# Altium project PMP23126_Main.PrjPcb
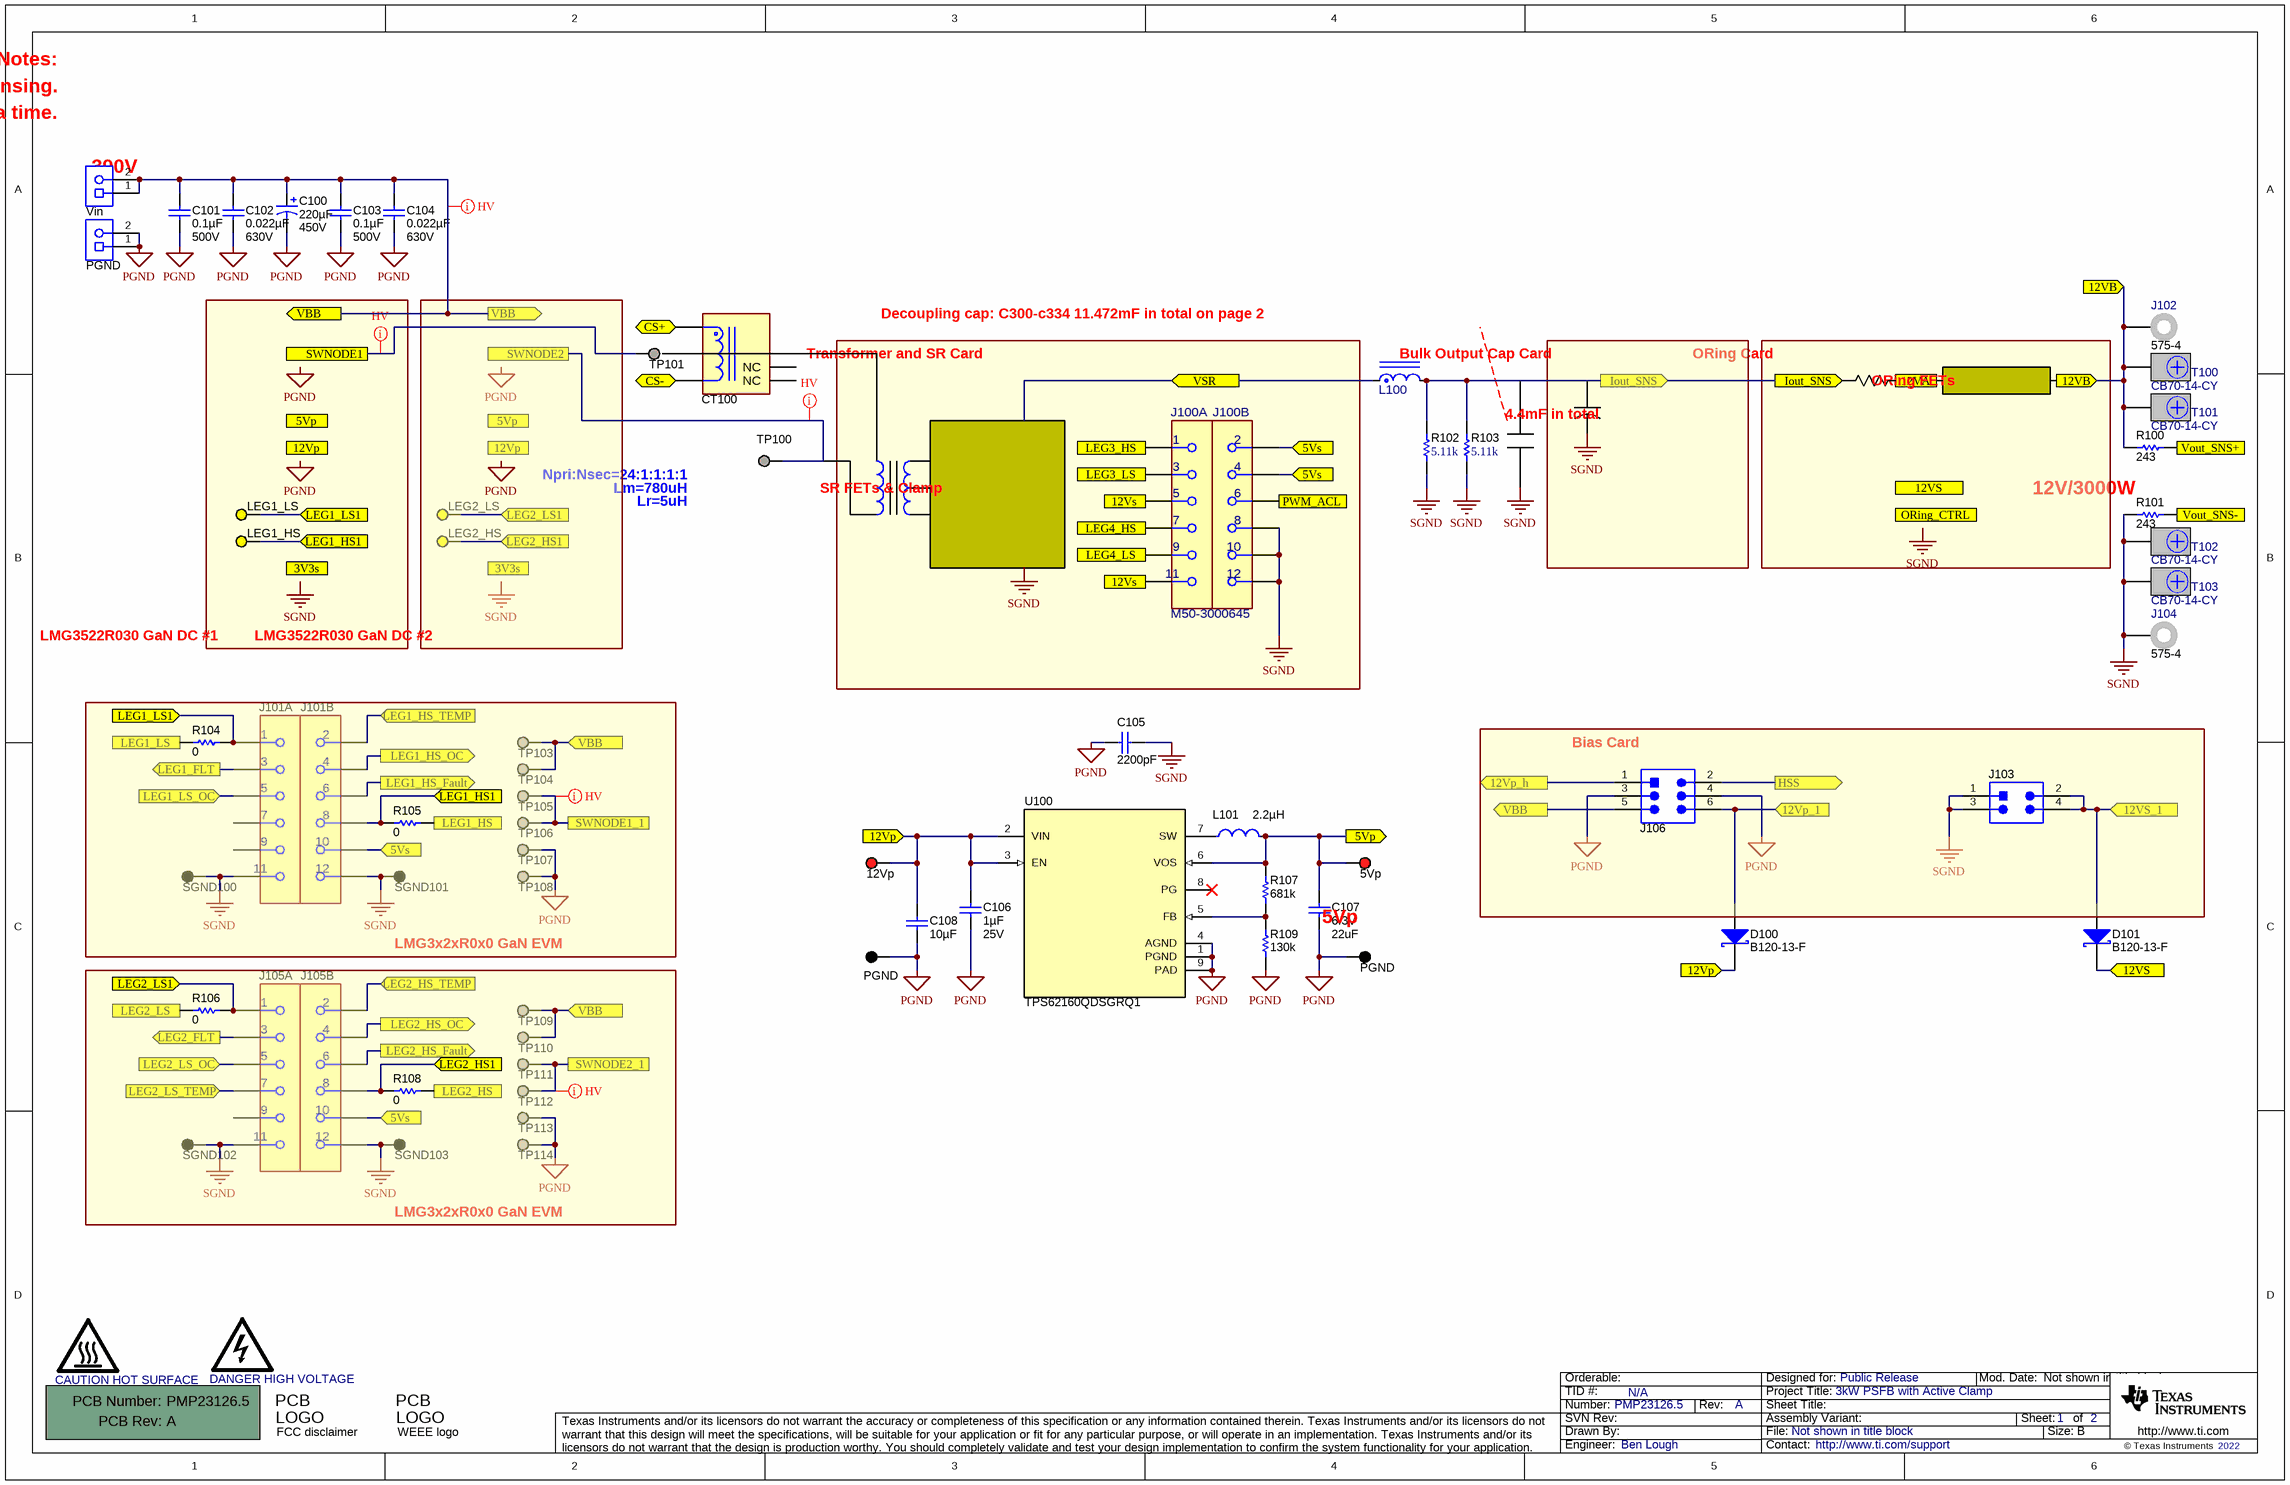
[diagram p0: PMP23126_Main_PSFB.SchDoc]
TID: N/A; TechSupport: http://www.ti.com/support; SCH_Rev: A; PRJ_Title: 3kW PSFB with Active Clamp; PRJ_Number: PMP23126.5; PRJ_Engineer: Ben Lough; PRJ_Customer: Public Release; PCB_Rev: A; PCB_Layout: Ben Lough; CopyrightYear: 2022
3 sheets, 168 parts. Net scope: flat (ports and power ports of the same name join across sheets).
Board file: PMP23126.5 Main Board.PcbDoc
Sheets:
  PMP23126_Main_PSFB.SchDoc
  PMP23126_Main_Controller.SchDoc
  Output_Decoupling.SchDoc

## Sheet PMP23126_Main_PSFB.SchDoc
size 431 x 279 mm; Date: Not shown in title block; ApprovedBy: Not shown in title block; CheckedBy: Not shown in title block; Author: Not shown in title block; CompanyName: Not shown in title block; Engineer: Not shown in title block; Organization: Not shown in title block; Address1: Not shown in title block; Address2: Not shown in title block; Address3: Not shown in title block; Address4: Not shown in title block; DocumentNumber: 1; Revision: Use project parameter SCH_Rev; SheetNumber: 1; SheetTotal: 2; PageSetup: Record=PageOptions¦CenterHorizontal=True¦CenterVertical=True¦PrintScale=1.00¦XCorrection=1.00¦YCorrection=1.00¦PrintKind=0¦BorderSize=5000000¦LeftOffset=0¦BottomOffset=0¦Orientation=2¦PaperLength=1000¦PaperWidth=1000¦Scale=100¦PaperSource=15¦PrintQuality=600¦MediaType=1¦DitherType=10¦PaperKind=Letter¦PrintScaleMode=1

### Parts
(Parts that share a designator on the sheet are numbered #1, #2 ... from top to bottom, then left to right.)
5Vp  5000  [Keystone5000]  (value not drawn)
12Vp  5000  [Keystone5000]  (value not drawn)
!PCB100  Printed Circuit Board  (value not drawn)  (mechanical)
C100  ValueDisplayed: 220µF  Value2: 450V  [TS-UP_3500x3000]  (hidden comment: LGU2W221MELC)
C101  ValueDisplayed: 0.1µF  Value2: 500V  [1812]  (hidden comment: VJ1812Y104KXEAT5Z)
C102  ValueDisplayed: 0.022µF  Value2: 630V  [1206]  (hidden comment: CL31B223KHHNNNE)
C103  ValueDisplayed: 0.1µF  Value2: 500V  [1812]  (hidden comment: VJ1812Y104KXEAT5Z)
C104  ValueDisplayed: 0.022µF  Value2: 630V  [1206]  (hidden comment: CL31B223KHHNNNE)
C105  ValueDisplayed: 2200pF  [E_900x700x900]  (hidden comment: DE6E3KJ222MN3A)
C106  Cap_F: 1µF  VDC_V: 25V  [0805_HV]  (hidden comment: C0805C105K3RACTU)
C107  VDC_V: 6.3V  ValueDisplayed: 22uF  [0805_HV]  (hidden comment: CL21A226KQQNNNE)
C108  ValueDisplayed: 10µF  [1206_180]  (hidden comment: GCM31CR71C106KA64L)
CT100  PAS6282NL  [FP-PAS6282NL_PTH_12MM5_4MM5-MFG]  (value not drawn)
D100  B120-13-F  [SMA]
D101  B120-13-F  [SMA]
J100#1  M50-3000645  [FP-M50-3000645_HDR12-MFG]  (part A of 2)
J100#2  M50-3000645  [FP-M50-3000645_HDR12-MFG]  (value not drawn)  (part B of 2)
J101  HLE-106-02-G-DV-BE-A  [FP-HLE-106-02-G-DV-BE-A_HDR12-MFG]  (value not drawn)  (parts A,B of 2)
J102  575-4  [Keystone_575-4]
J103  PBC02DAAN  [Sullins_PxC02DAAN]  (value not drawn)
J104  575-4  [Keystone_575-4]
J105  HLE-106-02-G-DV-BE-A  [FP-HLE-106-02-G-DV-BE-A_HDR12-MFG]  (value not drawn)  (parts A,B of 2)
J106  PBC03DAAN  [Sullins_PBC03DAAN]  (value not drawn)
L100  PAL6567.421NL  [FP-PAL6567.421NL_PTH_IND_34MM0_9MM5-MFG]  (value not drawn)
L101  Ind_H: 2.2µH  [FP-74438336010_SMD2-MFG]  (hidden comment: 74438336022)
LEG1_HS  5004  [Keystone5004]  (value not drawn)
LEG1_LS  5004  [Keystone5004]  (value not drawn)
LEG2_HS  5004  [Keystone5004]  (value not drawn)
LEG2_LS  5004  [Keystone5004]  (value not drawn)
LOGO100  CAUTION HOT SURFACE  [IEC_HotSurface_Small]  (no BOM)
LOGO101  DANGER HIGH VOLTAGE  [IEC_HighVoltage_Small]  (no BOM)
Logo102  FCC disclaimer  [FCC_disclaimer]  (no BOM)
Logo103  WEEE logo  [WEEE_Minimum]  (no BOM)
PGND#1  1715721  [PhoenixContact_1715721]  (value not drawn)
PGND#2  5001  [Keystone5001]  (value not drawn)
PGND#3  5001  [Keystone5001]  (value not drawn)
R100  ValueDisplayed: 243  [0603]  (hidden comment: CRCW0603243RFKEA)
R101  ValueDisplayed: 243  [0603]  (hidden comment: CRCW0603243RFKEA)
R102  ValueDisplayed: 5.11k  [1206]  (hidden comment: RC1206FR-075K11L)
R103  ValueDisplayed: 5.11k  [1206]  (hidden comment: RC1206FR-075K11L)
R104  ValueDisplayed: 0  [0603]  (hidden comment: CRCW06030000Z0EA)
R105  ValueDisplayed: 0  [0603]  (hidden comment: CRCW06030000Z0EA)
R106  ValueDisplayed: 0  [0603]  (hidden comment: CRCW06030000Z0EA)
R107  ValueDisplayed: 681k  [0402]  (hidden comment: CRCW0402681KFKED)
R108  ValueDisplayed: 0  [0603]  (hidden comment: CRCW06030000Z0EA)
R109  ValueDisplayed: 130k  [0402]  (hidden comment: CRCW0402130KFKED)
SGND100  5001  [Keystone5001]  (value not drawn)
SGND101  5001  [Keystone5001]  (value not drawn)
SGND102  5001  [Keystone5001]  (value not drawn)
SGND103  5001  [Keystone5001]  (value not drawn)
T100  CB70-14-CY  [CB70-14-CY]
T101  CB70-14-CY  [CB70-14-CY]
T102  CB70-14-CY  [CB70-14-CY]
T103  CB70-14-CY  [CB70-14-CY]
TP100  Suggest using a net name here  [Mill-Max_0312-0-15-15-34-27-10-0]  (value not drawn)
TP101  Suggest using a net name here  [Mill-Max_0312-0-15-15-34-27-10-0]  (value not drawn)
TP103  Suggest using a net name here  [Mill-Max_0312-0-15-15-34-27-10-0]  (value not drawn)
TP104  Suggest using a net name here  [Mill-Max_0312-0-15-15-34-27-10-0]  (value not drawn)
TP105  Suggest using a net name here  [Mill-Max_0312-0-15-15-34-27-10-0]  (value not drawn)
TP106  Suggest using a net name here  [Mill-Max_0312-0-15-15-34-27-10-0]  (value not drawn)
TP107  Suggest using a net name here  [Mill-Max_0312-0-15-15-34-27-10-0]  (value not drawn)
TP108  Suggest using a net name here  [Mill-Max_0312-0-15-15-34-27-10-0]  (value not drawn)
TP109  Suggest using a net name here  [Mill-Max_0312-0-15-15-34-27-10-0]  (value not drawn)
TP110  Suggest using a net name here  [Mill-Max_0312-0-15-15-34-27-10-0]  (value not drawn)
TP111  Suggest using a net name here  [Mill-Max_0312-0-15-15-34-27-10-0]  (value not drawn)
TP112  Suggest using a net name here  [Mill-Max_0312-0-15-15-34-27-10-0]  (value not drawn)
TP113  Suggest using a net name here  [Mill-Max_0312-0-15-15-34-27-10-0]  (value not drawn)
TP114  Suggest using a net name here  [Mill-Max_0312-0-15-15-34-27-10-0]  (value not drawn)
U100  TPS62160QDSGRQ1  [DSG0008A]
Vin  1715721  [PhoenixContact_1715721]  (value not drawn)

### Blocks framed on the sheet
LMG3522R030 GaN DC #1: LEG1_HS LEG1_LS
LMG3522R030 GaN DC #2: LEG2_HS LEG2_LS
LMG3x2xR0x0 GaN EVM: J101 R104 R105 SGND100 SGND101 TP103-TP108
Bias Card: J103 J106
LMG3x2xR0x0 GaN EVM: J105 R106 R108 SGND102 SGND103 TP109-TP114

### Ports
3V3s (in), 5Vp (in), 5Vp (out), 5Vs (in), 12VA (out), 12VB (in), 12Vp (in), 12Vp_1 (in), 12Vp_h (out), 12VS (in), 12Vs (in), 12VS_1 (in), CS+ (bidir), CS- (bidir), HSS (out), Iout_SNS (out), LEG1_FLT (out), LEG1_HS1 (in), LEG1_HS (in), LEG1_HS_Fault (out), LEG1_HS_OC (out), LEG1_HS_TEMP (in), LEG1_LS1 (in), LEG1_LS (in), LEG1_LS_OC (in), LEG2_FLT (out), LEG2_HS1 (in), LEG2_HS (in), LEG2_HS_Fault (out), LEG2_HS_OC (out), LEG2_HS_TEMP (in), LEG2_LS1 (in), LEG2_LS (in), LEG2_LS_OC (in), LEG2_LS_TEMP (in), LEG3_HS (out), LEG3_LS (out), LEG4_HS (out), LEG4_LS (out), ORing_CTRL (in), PWM_ACL (out), SWNODE1, SWNODE1_1, SWNODE2, SWNODE2_1, VBB (in), VBB (out), Vout_SNS+ (out), Vout_SNS- (out), VSR (in)

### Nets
PGND: C100.2(-) C101.2 C102.2 C103.2 C104.2 C105.1 C106.2 C107.2 C108.2 J106.3 J106.4 PGND#1.1 PGND#1.2 PGND#2.1 PGND#3.1 R109.1 TP107.1 TP108.1 TP113.1 TP114.1 U100.1(PGND) U100.4(AGND) U100.9(PAD)
SGND: C105.2 J100#2.8 J100#2.10 J100#2.12 J101.11 J101.12 J103.1 J103.3 J104.1 J105.11 J105.12 R101.1 R102.1 R103.1 SGND100.1 SGND101.1 SGND102.1 SGND103.1 T102.1 T103.1
5Vp: 5Vp.1 C107.1 L101.2 R107.2 U100.6(VOS) ; port 5Vp
5Vs: J100#2.2 J100#2.4 J101.10 J105.10 ; port 5Vs
12VB: J102.1 R100.1 T100.1 T101.1 ; port 12VB
12Vp: 12Vp.1 C106.1 C108.1 D100.1(K) U100.2(VIN) U100.3(EN) ; port 12Vp
12Vp_1: D100.2(A) J106.6 ; port 12Vp_1
12Vp_h: J106.1 ; port 12Vp_h
12VS: D101.1(K) J100#1.5 J100#1.11 ; port 12VS, port 12Vs
12VS_1: D101.2(A) J103.2 J103.4 ; port 12VS_1
CS+: CT100.1 ; port CS+
CS-: CT100.3 ; port CS-
HSS: J106.2 ; port HSS
Iout_SNS: L100.2(F) R102.2 R103.2 ; port Iout_SNS
LEG1_FLT: J101.3 ; port LEG1_FLT
LEG1_HS: R105.2 ; port LEG1_HS
LEG1_HS1: J101.8 LEG1_HS.1 R105.1 ; port LEG1_HS1
LEG1_HS_Fault: J101.6 ; port LEG1_HS_Fault
LEG1_HS_OC: J101.4 ; port LEG1_HS_OC
LEG1_HS_TEMP: J101.2 ; port LEG1_HS_TEMP
LEG1_LS: R104.1 ; port LEG1_LS
LEG1_LS1: J101.1 LEG1_LS.1 R104.2 ; port LEG1_LS1
LEG1_LS_OC: J101.5 ; port LEG1_LS_OC
LEG2_FLT: J105.3 ; port LEG2_FLT
LEG2_HS: R108.2 ; port LEG2_HS
LEG2_HS1: J105.8 LEG2_HS.1 R108.1 ; port LEG2_HS1
LEG2_HS_Fault: J105.6 ; port LEG2_HS_Fault
LEG2_HS_OC: J105.4 ; port LEG2_HS_OC
LEG2_HS_TEMP: J105.2 ; port LEG2_HS_TEMP
LEG2_LS: R106.1 ; port LEG2_LS
LEG2_LS1: J105.1 LEG2_LS.1 R106.2 ; port LEG2_LS1
LEG2_LS_OC: J105.5 ; port LEG2_LS_OC
LEG2_LS_TEMP: J105.7 ; port LEG2_LS_TEMP
LEG3_HS: J100#1.1 ; port LEG3_HS
LEG3_LS: J100#1.3 ; port LEG3_LS
LEG4_HS: J100#1.7 ; port LEG4_HS
LEG4_LS: J100#1.9 ; port LEG4_LS
PWM_ACL: J100#2.6 ; port PWM_ACL
SWNODE1: TP101.1 ; port SWNODE1
SWNODE1_1: TP105.1 TP106.1 ; port SWNODE1_1
SWNODE2: TP100.1 ; port SWNODE2
SWNODE2_1: TP111.1 TP112.1 ; port SWNODE2_1
VBB: C100.1(+) C101.1 C102.1 C103.1 C104.1 J106.5 TP103.1 TP104.1 TP109.1 TP110.1 Vin.1 Vin.2 ; port VBB
Vout_SNS+: R100.2 ; port Vout_SNS+
Vout_SNS-: R101.2 ; port Vout_SNS-
VSR: L100.1(S) ; port VSR
NetL101_1: L101.1 U100.7(SW)
NetR107_1: R107.1 R109.2 U100.5(FB)

Not connected (* = marked no-connect by the designer): CT100 2(NC) 4(NC); J101 7 9; J105 9; U100 8(PG)*

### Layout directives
net class HV: SWNODE1, SWNODE1_1, SWNODE2, SWNODE2_1, VBB

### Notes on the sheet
- Notes:
- 1. Transformer winding go through CT100 for current sensing.
- 2. Use either LMG3x2xR030 EVM or customized daughter card at a time.
- 390V
- Transformer and SR Card
- Decoupling cap: C300-c334 11.472mF in total on page 2
- Bulk Output Cap Card
- ORing Card
- 4.4mF in total
- ORing FETs
- (near TP100) Npri:Nsec=24:1:1:1:1
- (near TP100) Lm=780uH
- (near TP100) Lr=5uH
- SR FETs & Clamp
- (near R101) 12V/3000W
- 5Vp
- Labels drawn without touching a wire or pin: PGND, SGND

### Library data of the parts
5Vp 12Vp = 5000: Test Point, Miniature, Red, TH; Manufacturer: Keystone; CompType: Test Point Loop; ContactFinish: Silver; Green_Lifecycle: Active; Green_REACh: Passed
!PCB100 = CMP-0003618-2: Manufacturer: Any; PartNumber: PMP23126.5
C100 = ECOS2GP331EX: CAP ALUM 220UF 20% 450V SNAP; Manufacturer: Nichicon; Polarized: Y; CompType: Capacitor; U/M: EA; Tolerance_%: 20; VDC_V: 450; IRMS_A: 1.9; TaMin_C: -25; Cap_Case: 35x30mm; SizeAreaWB_mm2: 1369; SizeArea_mm2: 1225; SizeX_mm: 35; SizeZ_mm: 32; AEC Category: Q200
C101 C103 = VJ1812Y104KXEAT5Z: CAP, CERM, 0.1 µF, 500 V,+/- 10%, X7R, 1812; Manufacturer: Vishay-Vitramon; Polarized: N; CompType: Capacitor; Value: 0.1uF; U/M: EA; Cap_F: 0.0000001; Tolerance_%: 10; VDC_V: 500; TaMin_C: -55; TaMax_C: 125; SizeArea_mm2: 14.4; SizeAreaWB_mm2: 23.1; SizeX_mm: 4.5; SizeY_mm: 3.2; SizeZ_mm: 1.35; AEC Category: Q200
C102 C104 = VJ1206Y223KXGAT5Z: CAP, CERM, 0.022 µF, 630 V,+/- 10%, X7R, 1206; Manufacturer: Samsung Electro-Mechanics; Polarized: N; CompType: Capacitor; Value: 0.022uF; U/M: EA; Cap_F: 0.000000022; Tolerance_%: 10; VDC_V: 630; TaMin_C: -55; TaMax_C: 125; SizeArea_mm2: 5.12; SizeAreaWB_mm2: 10.92; SizeX_mm: 3.2; SizeY_mm: 1.6; SizeZ_mm: 1.35; AEC Category: Q200
C105 = DE6E3KJ222MN3A: CAP, CERM, 2200 pF, 300 V, +/- 20%, E, TH, 2- Leads, Body 9x7mm, Pin Spacing 7.5mm; Manufacturer: MuRata; Polarized: N; CompType: Capacitor; Value: 2200pF; U/M: EA; Cap_F: 0.0000000022; Tolerance_%: 20; Value1: Unknown; VDC_V: 300; Value2: 300V; TaMin_C: -40; TaMax_C: 125; Cap_Case: 9x7x9mm; SizeArea_mm2: 63; SizeAreaWB_mm2: 99; SizeX_mm: 9; SizeY_mm: 7; SizeZ_mm: 12; AEC Category: Q200
C106 = CMP-0007728-2: CAP, CERM, 1 uF, 25 V, +/- 10%, X7R, 0805; Manufacturer: Kemet; TaMin_C: -55°C; Polarized: N; SizeAreaWB_mm2: 6.75; Value1: Unknown; U/M: EA; Value: 1uF; TaMax_C: 125°C; SizeZ_mm: 1.45; SizeX_mm: 2; SizeY_mm: 1.25; Cap_Case: 0805; SizeArea_mm2: 2.5; CompType: Capacitor; AEC Category: Q200
C107 = CMP-0007989-2: CAP, CERM, 22 uF, 6.3 V, +/- 10%, X5R, 0805; Manufacturer: Samsung Electro-Mechanics; TaMin_C: -55°C; Polarized: N; SizeAreaWB_mm2: 6.75; Value1: Unknown; U/M: EA; Value: 22uF; TaMax_C: 85°C; SizeZ_mm: 1.45; SizeX_mm: 2; SizeY_mm: 1.25; Cap_Case: 0805; SizeArea_mm2: 2.5; CompType: Capacitor; Cap_F: 22µF; AEC Category: Q200
C108 = GCM31CR71C106KA64L: CAP, CERM, 10 µF, 16 V,+/- 10%, X7R, AEC-Q200 Grade 1, 1206; Manufacturer: MuRata; Polarized: N; CompType: Capacitor; Value: 10uF; U/M: EA; Cap_F: 0.00001; Tolerance_%: 10; VDC_V: 16; Value2: 16V; TaMin_C: -55; TaMax_C: 125; Cap_Case: 1206; SizeArea_mm2: 5.12; SizeAreaWB_mm2: 10.92; SizeX_mm: 3.2; SizeY_mm: 1.6; SizeZ_mm: 1.8; AEC Category: Q200; AEC Qualified: Y; AEC Grade: 1; Green_Lifecycle: Active; Green_REACh: Passed
CT100 = CMP-0091119-1: Inductor PTH 3.3mH 300mOhm; Manufacturer: Pulse Electronics; SizeZ_mm: 13.5mm; AEC Qualified: No; DCR_ohm: 3d; Test Frequency: 100kHz
D100 D101 = CMP-0028374-2: Diode, Schottky, 20 V, 1 A, SMA; Manufacturer: Diodes Inc.; TJmax_C: 150°C; Value2: 0.5V; Green_Lifecycle: Active; SizeZ_mm: 2.87; Vr_V: 20V; Green_REACh: Passed; AEC Category: Q101; SizeX_mm: 5.59; SizeY_mm: 2.92; Value1: 1A; Vf_V: 500mV; SizeArea_mm2: 16.3228; RJC_CperW: 20; Value: 20V; SizeAreaWB_mm2: 37.3428
J100#1 J100#2 = CMP-0094055-1: 12 Position Receptacle Connector 0.050" (1.27mm) Through Hole Gold; Manufacturer: Harwin; AEC Qualified: No; Is Female: yes; ContactFinish: Gold,Nickel; SizeZ_mm: 4.55mm; Current_A: 1A; Conn Gender: Female; Conn Orientation: Vertical; Row_Count: 2
J101 J105 = CMP-0089984-1: 12 Position Receptacle, Bottom Entry Connector  Surface Mount; Manufacturer: Samtec; Current_A: 4.1A; Conn Orientation: Vertical; DUT-Pitch_mm: 2.54mm; Conn Gender: Female; SizeZ_mm: 3.79mm; Is Female: yes; AEC Qualified: No; ContactFinish: Gold,Nickel; Voltage_V: 400V; Row_Count: 2
J102 J104 = CMP-0055165-2: Standard Banana Jack, Uninsulated, 5.5mm; Manufacturer: Keystone; CT: TRUE; Green_REACh: Passed; CNHeader: FALSE; Green_Lifecycle: Active
J103 = CMP-0054598-1: Header, 2.54mm, 2x2, Gold, TH; Manufacturer: Sullins Connector Solutions; Cert_UL: Y; CNHeader: TRUE; CT: FALSE; Current_A: 3A; Gender: Male; Pitch_mm: 2.54; Row_Count: 2; Shrouded: N; Voltage_V: 1.8kV
J106 = CMP-0054565-2: Header, 100mil, 3x2, Gold, TH; Manufacturer: Sullins Connector Solutions; Cert_UL: Y; Current_A: 3A; Gender: Male; Green_Lifecycle: Active; Green_REACh: Passed; Pitch_mm: 2.54; Row_Count: 2; Shrouded: N; Voltage_V: 1.8kV
L100 = CMP-0093530-1: INDUCTOR, POWER, EP33, TH 0.42uH 20% 10kHz 0.06mOhm DCR MAX 300A Isat; Manufacturer: Pulse; Ind_H: 420nH; AEC Qualified: No; DCR_ohm: 60µ; SizeZ_mm: 25mm
L101 = CMP-0087867-1: 2.2µH Shielded Molded Inductor 2.4A 67mOhm Max 2-SMD; Manufacturer: Wurth Electronics; SizeZ_mm: 2mm; Material: Metal Composite; Isat: 4.3A; Symbol Name: SYM-74438336010; DCR_ohm: 0.032; AEC Grade: Grade 1; AEC Qualified: Yes
LEG1_HS LEG1_LS LEG2_HS LEG2_LS = 5004: Test Point, Miniature, Yellow, TH; Manufacturer: Keystone; CompType: Test Point Loop; ContactFinish: Silver; Green_Lifecycle: Active; Green_REACh: Passed
LOGO100 = CMP-0074837-1: IEC 61010-1 Hot Surface Warning; Library Reference: IEC_HotSurface; SymbolCreator: a0412235
LOGO101 = CMP-0074835-1: IEC 61010-1 High Voltage Warning; Library Reference: IEC_HighVoltage; SymbolCreator: a0412235
Logo102 = CMP-0074847-1: FCC_disclaimer; Library Reference: Logo
Logo103 = CMP-0074769-1
PGND#1 Vin = CMP-0055471-1: Terminal Block, 5.08 mm, 2x1, TH; Manufacturer: Phoenix Contact; Cert_VDE: Y; CNHeader: FALSE; Current_A: 17.5A; Green_Lifecycle: Not Set; Gender: Female; Cert_CULUS: N; Green_REACh: Incomplete; Voltage_V: 400V; Row_Count: 1; Pitch_mm: 5.08; ContactFinish: Tin; CT: TRUE
PGND#2 PGND#3 SGND100-SGND103 = 5001: Test Point, Miniature, Black, TH; Manufacturer: Keystone; CompType: Test Point Loop; ContactFinish: Silver; Green_Lifecycle: Active; Green_REACh: Passed
R100 R101 = CRCW0603243RFKEA: RES, 243, 1%, 0.1 W, 0603; Manufacturer: Vishay-Dale; CompType: Resistor; Value: 243; Value_Code: 243R; Tolerance_%: 1; Power_W: 0.1; Value2: 0.1W; VDC_V: 75; TempCo: 100 ppm/C; SizeArea_mm2: 1.28; SizeX_mm: 1.6; SizeY_mm: 0.8; EIA_Code: E96; U/M: EA; AEC Category: Q200
R102 R103 = CMP-0018389-2: RES, 5.11 k, 1%, 0.25 W, 1206; Manufacturer: Yageo America; Power_W: 250mW; TempCo: 100 ppm/C; Value_Code: 5k11; U/M: EA; Value: 5.11k; EIA_Code: E96; SizeX_mm: 3.2; SizeY_mm: 1.6; SizeZ_mm: 1.35; Value2: 0.25W; SizeArea_mm2: 5.12; VDC_V: 200V; AEC Category: Q200
R104-R106 R108 = CRCW06030000Z0EA: RES, 0, 5%, 0.1 W, 0603; Manufacturer: Vishay-Dale; CompType: Resistor; Value: 0; Value_Code: 0000; Tolerance_%: 5; Power_W: 0.1; Value2: 0.1W; VDC_V: 75; TempCo: 200 ppm/C; SizeArea_mm2: 1.28; SizeX_mm: 1.6; SizeY_mm: 0.8; SizeZ_mm: 1; EIA_Code: E24; U/M: EA; AEC Category: Q200; Green_Lifecycle: Active; Green_REACh: Passed
R107 = CMP-0026504-2: RES, 681 k, 1%, 0.063 W, AEC-Q200 Grade 0, 0402; Manufacturer: Vishay-Dale; Power_W: 63mW; TempCo: 100 ppm/C; Value: 681k; EIA_Code: E96; SizeX_mm: 1; SizeY_mm: 0.5; SizeZ_mm: 0.6; Value2: 0.063W; CompType: Resistor; AEC Qualified: Y; VDC_V: 50V; AEC Category: Q200; AEC Grade: 0
R109 = CMP-0025997-3: RES, 130 k, 1%, 0.063 W, AEC-Q200 Grade 0, 0402; Manufacturer: Vishay-Dale; Power_W: 63mW; TempCo: 100 ppm/C; Value: 130k; EIA_Code: E96; SizeX_mm: 1; SizeY_mm: 0.5; SizeZ_mm: 0.6; Value2: 0.063W; CompType: Resistor; AEC Qualified: Y; VDC_V: 50V; AEC Category: Q200; AEC Grade: 0
T100-T103 = CMP-0055443-2: Terminal 90A Lug; Manufacturer: Panduit; Green_Lifecycle: Not Set; Cert_CULUS: Y; Green_REACh: Incomplete; Voltage_V: 600V; CompType: Screw Terminal; ContactFinish: Copper
TP100 TP101 TP103-TP114 = 0312-0-15-15-34-27-10-0: Pin Receptacle, .032-.046" .075" Dia, Gold, TH; Manufacturer: Mill-Max; Gender: Female
U100 = CMP-0067100-2: 3V-17V 1A Automotive Step-Down Converters in 2x2SON, DSG0008A (WSON-8); Alternate PartNumber: TPS62160QDSGTQ1; Manufacturer: Texas Instruments; SizeZ_mm: 0.8; SizeX_mm: 2.0; SizeArea_mm2: 4.0; CompType: IC; U/M: EA; SizeAreaWB_mm2: 9.0

## Sheet PMP23126_Main_Controller.SchDoc
size 431 x 279 mm; Date: Not shown in title block; ApprovedBy: Not shown in title block; CheckedBy: Not shown in title block; Author: Not shown in title block; CompanyName: Not shown in title block; Engineer: Not shown in title block; Organization: Not shown in title block; Address1: Not shown in title block; Address2: Not shown in title block; Address3: Not shown in title block; Address4: Not shown in title block; DocumentNumber: 2; Revision: Use project parameter SCH_Rev; SheetNumber: 2; SheetTotal: 2; PageSetup: Record=PageOptions¦CenterHorizontal=True¦CenterVertical=True¦PrintScale=1.00¦XCorrection=1.00¦YCorrection=1.00¦PrintKind=0¦BorderSize=5000000¦LeftOffset=0¦BottomOffset=0¦Orientation=2¦PaperLength=1000¦PaperWidth=1000¦Scale=100¦PaperSource=15¦PrintQuality=600¦MediaType=1¦DitherType=10¦PaperKind=Letter¦PrintScaleMode=1
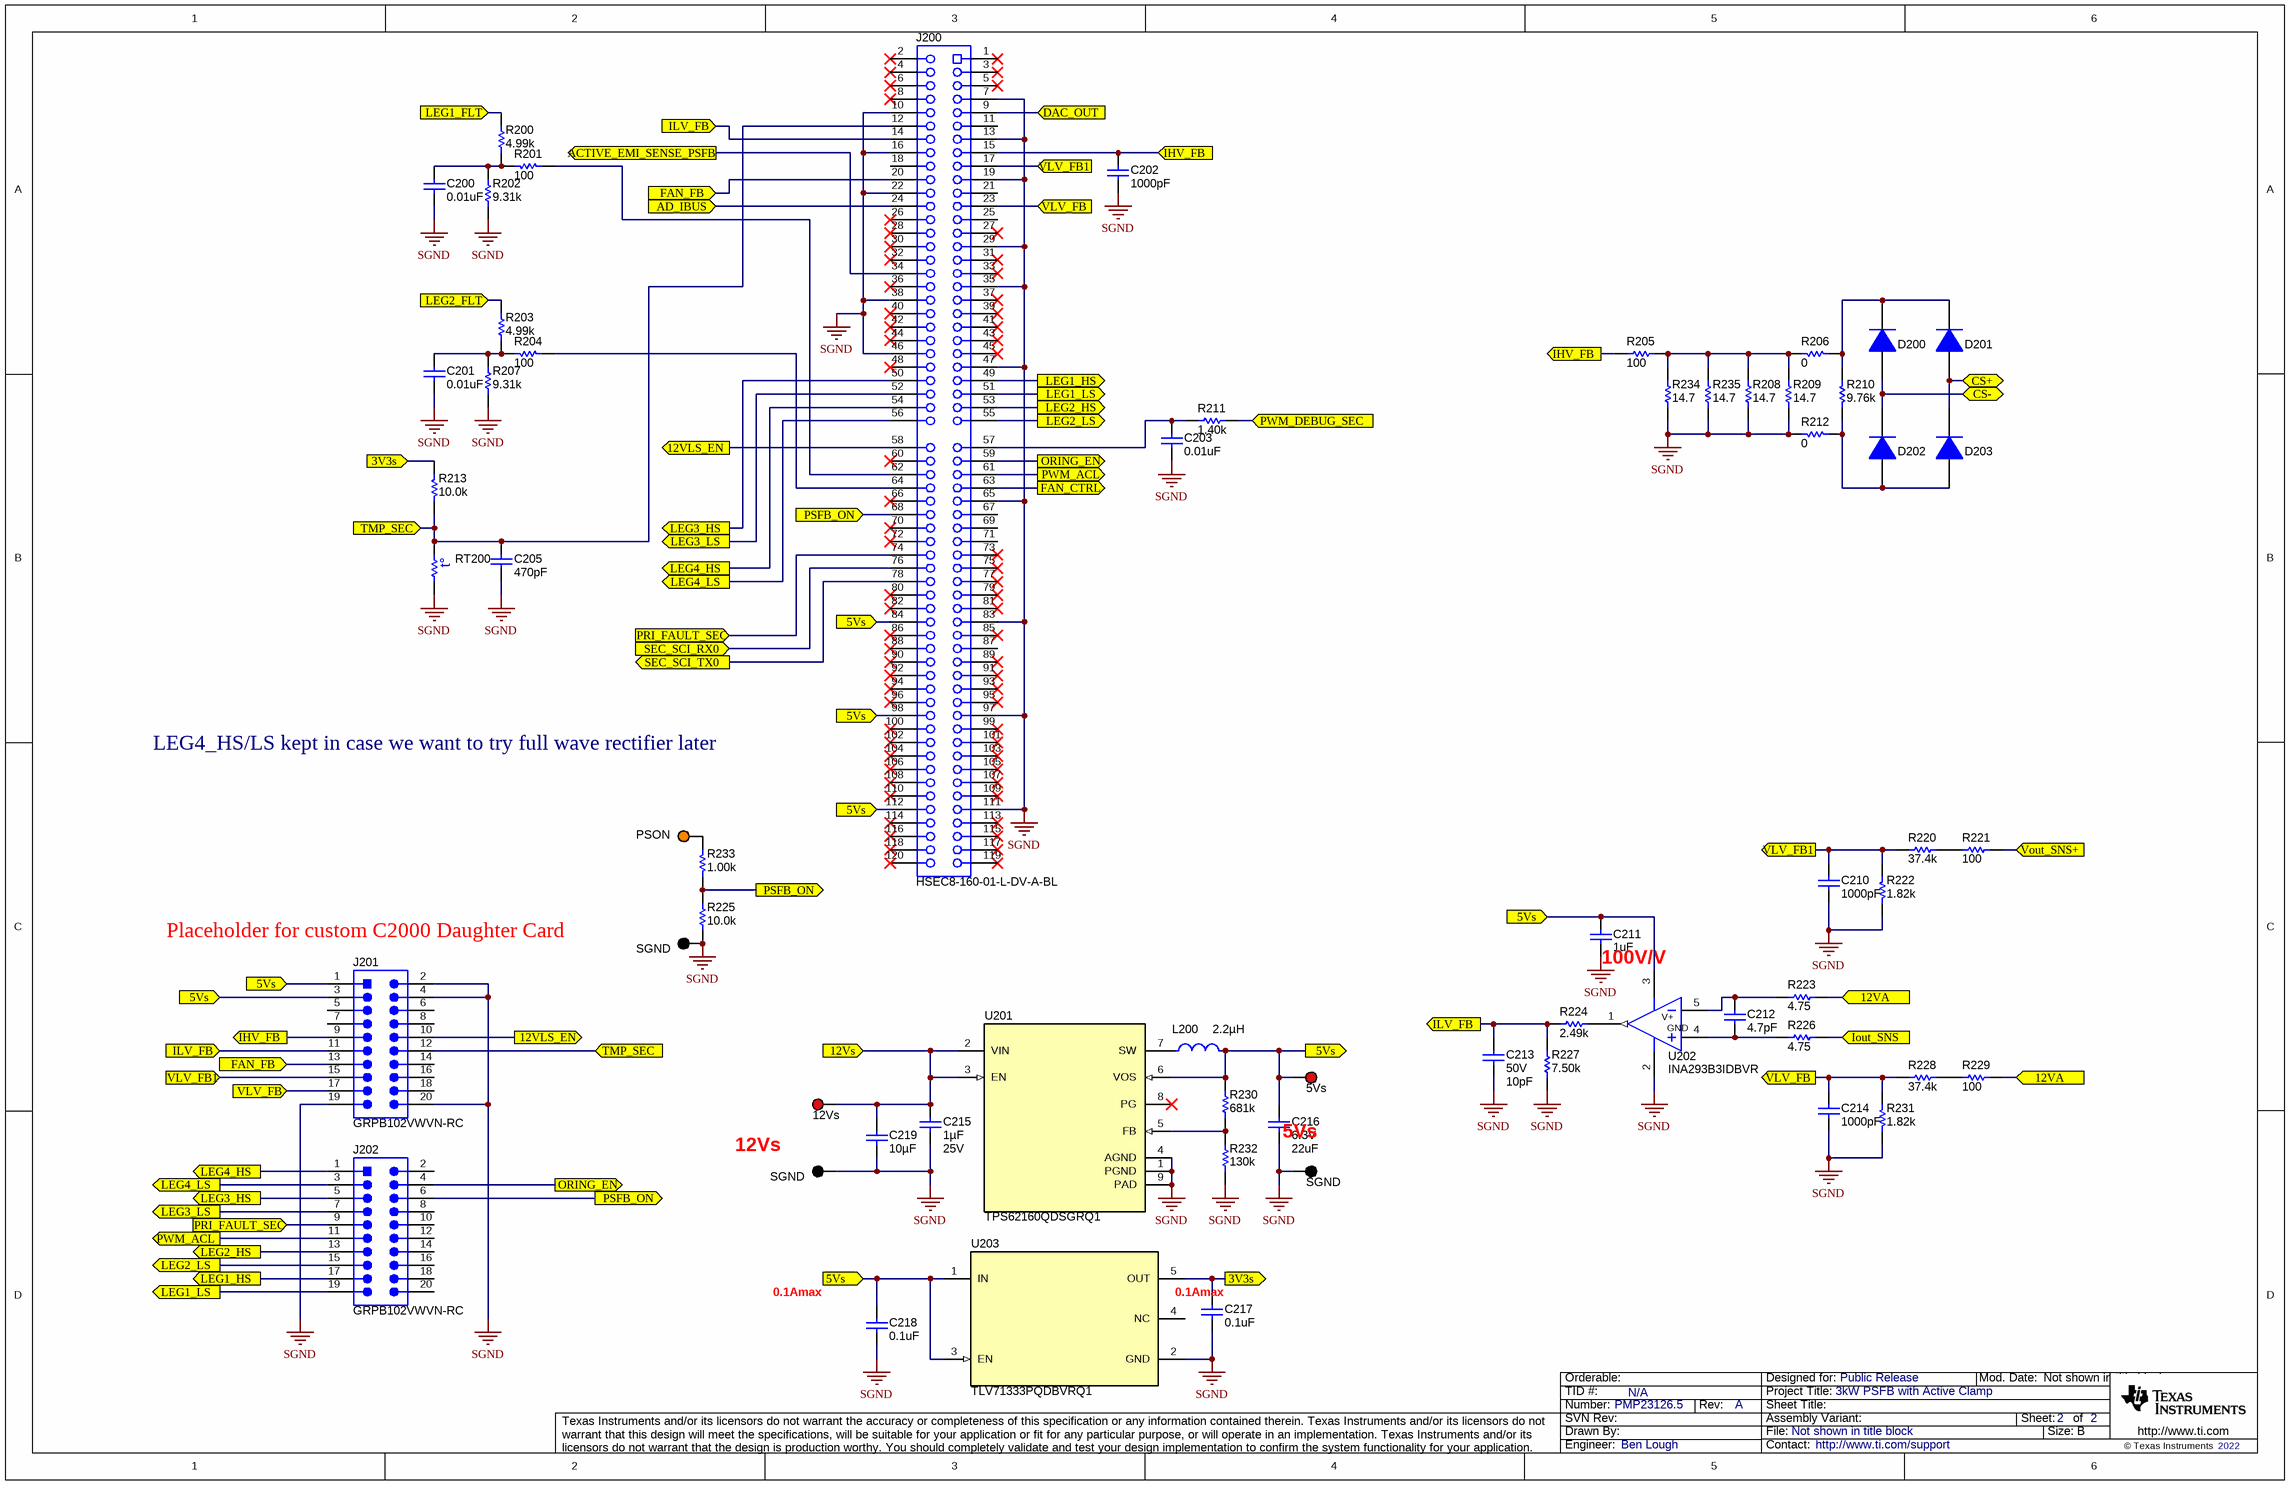
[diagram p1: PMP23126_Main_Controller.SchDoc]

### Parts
(Parts that share a designator on the sheet are numbered #1, #2 ... from top to bottom, then left to right.)
5Vs  5000  [Keystone5000]  (value not drawn)
12Vs  5000  [Keystone5000]  (value not drawn)
C200  ValueDisplayed: 0.01uF  [0402]  (hidden comment: GRM155R70J103KA01D)
C201  ValueDisplayed: 0.01uF  [0402]  (hidden comment: GRM155R70J103KA01D)
C202  ValueDisplayed: 1000pF  [0402]  (hidden comment: 885012205044)
C203  ValueDisplayed: 0.01uF  [0402]  (hidden comment: GRM155R70J103KA01D)
C205  ValueDisplayed: 470pF  [0402]  (hidden comment: CGA2B2X7R1H471K050BA)
C210  ValueDisplayed: 1000pF  [0603]  (hidden comment: 06035A102KAT2A)
C211  ValueDisplayed: 1uF  [0603]  (hidden comment: C1608X7R1E105K080AB)
C212  ValueDisplayed: 4.7pF  [0402]  (hidden comment: GRM1555C1E4R7CA01D)
C213  VDC_V: 50V  ValueDisplayed: 10pF  [0402]  (hidden comment: 04025U100CAT2A)
C214  ValueDisplayed: 1000pF  [0603]  (hidden comment: 06035A102KAT2A)
C215  Cap_F: 1µF  VDC_V: 25V  [0805_HV]  (hidden comment: C0805C105K3RACTU)
C216  VDC_V: 6.3V  ValueDisplayed: 22uF  [0805_HV]  (hidden comment: CL21A226KQQNNNE)
C217  ValueDisplayed: 0.1uF  [0402]  (hidden comment: GRM155R70J104KA01D)
C218  ValueDisplayed: 0.1uF  [0402]  (hidden comment: GRM155R70J104KA01D)
C219  ValueDisplayed: 10µF  [1206_180]  (hidden comment: GCM31CR71C106KA64L)
D200  BAS316,115  [SOD-323]  (value not drawn)
D201  BAS316,115  [SOD-323]  (value not drawn)
D202  BAS316,115  [SOD-323]  (value not drawn)
D203  BAS316,115  [SOD-323]  (value not drawn)
J200  HSEC8-160-01-L-DV-A-BL  [controlCARD-120HSEC]
J201  GRPB102VWVN-RC  [Sullins_GRPB102VWVN]
J202  GRPB102VWVN-RC  [Sullins_GRPB102VWVN]
L200  Ind_H: 2.2µH  [FP-74438336010_SMD2-MFG]  (hidden comment: 74438336022)
PSON  5003  [Keystone5003]  (value not drawn)
R200  ValueDisplayed: 4.99k  [0402]  (hidden comment: CRCW04024K99FKED)
R201  ValueDisplayed: 100  [0603]  (hidden comment: CRCW0603100RFKEA)
R202  ValueDisplayed: 9.31k  [0402]  (hidden comment: CRCW04029K31FKED)
R203  ValueDisplayed: 4.99k  [0402]  (hidden comment: CRCW04024K99FKED)
R204  ValueDisplayed: 100  [0603]  (hidden comment: CRCW0603100RFKEA)
R205  ValueDisplayed: 100  [0402]  (hidden comment: ATC504L1000FTNCFT)
R206  ValueDisplayed: 0  [0402]  (hidden comment: CRCW04020000Z0ED)
R207  ValueDisplayed: 9.31k  [0402]  (hidden comment: CRCW04029K31FKED)
R208  ValueDisplayed: 14.7  [1206]  (hidden comment: CRCW120614R7FKEA)
R209  ValueDisplayed: 14.7  [1206]  (hidden comment: CRCW120614R7FKEA)
R210  ValueDisplayed: 9.76k  [0603]  (hidden comment: RC0603FR-079K76L)
R211  value 1.40k  [0402]  (hidden comment: CRCW04021K40FKED)
R212  ValueDisplayed: 0  [0402]  (hidden comment: CRCW04020000Z0ED)
R213  ValueDisplayed: 10.0k  [0402]  (hidden comment: CRCW040210K0FKED)
R220  ValueDisplayed: 37.4k  [1206]  (hidden comment: CRCW120637K4FKEA)
R221  ValueDisplayed: 100  [0603]  (hidden comment: CRCW0603100RFKEA)
R222  ValueDisplayed: 1.82k  [0603]  (hidden comment: RC0603FR-071K82L)
R223  ValueDisplayed: 4.75  [0603]  (hidden comment: RC0603FR-074R75L)
R224  ValueDisplayed: 2.49k  [0603]  (hidden comment: CRCW06032K49FKEA)
R225  ValueDisplayed: 10.0k  [1206]  (hidden comment: CRCW120610K0FKEA)
R226  ValueDisplayed: 4.75  [0603]  (hidden comment: RC0603FR-074R75L)
R227  ValueDisplayed: 7.50k  [0603]  (hidden comment: CRCW06037K50FKEA)
R228  ValueDisplayed: 37.4k  [1206]  (hidden comment: CRCW120637K4FKEA)
R229  ValueDisplayed: 100  [0603]  (hidden comment: CRCW0603100RFKEA)
R230  ValueDisplayed: 681k  [0402]  (hidden comment: CRCW0402681KFKED)
R231  ValueDisplayed: 1.82k  [0603]  (hidden comment: RC0603FR-071K82L)
R232  ValueDisplayed: 130k  [0402]  (hidden comment: CRCW0402130KFKED)
R233  ValueDisplayed: 1.00k  [0402]  (hidden comment: CRCW04021K00FKED)
R234  ValueDisplayed: 14.7  [1206]  (hidden comment: CRCW120614R7FKEA)
R235  ValueDisplayed: 14.7  [1206]  (hidden comment: CRCW120614R7FKEA)
RT200  TMP6131DECR  [DEC0002A]  (value not drawn)
SGND#1  5001  [Keystone5001]  (value not drawn)
SGND#2  5001  [Keystone5001]  (value not drawn)
SGND#3  5001  [Keystone5001]  (value not drawn)
U201  TPS62160QDSGRQ1  [DSG0008A]
U202  INA293B3IDBVR  [DBV0005A_L]
U203  TLV71333PQDBVRQ1  [DBV0005A_N]

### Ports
3V3s (in), 3V3s (out), 5Vs (in), 5Vs (out), 12VA (in), 12VLS_EN (out), 12Vs (in), ACTIVE_EMI_SENSE_PSFB (out), AD_IBUS (in), CS+ (bidir), CS- (bidir), DAC_OUT (in), FAN_CTRL (out), FAN_FB (in), IHV_FB (in), IHV_FB (out), ILV_FB (in), ILV_FB (out), Iout_SNS (in), LEG1_FLT (in), LEG1_HS (out), LEG1_LS (out), LEG2_FLT (in), LEG2_HS (out), LEG2_LS (out), LEG3_HS (out), LEG3_LS (out), LEG4_HS (out), LEG4_LS (out), ORING_EN (out), PRI_FAULT_SEC (in), PSFB_ON (in), PSFB_ON (out), PWM_ACL (out), PWM_DEBUG_SEC (in), SEC_SCI_RX0 (in), SEC_SCI_TX0 (out), TMP_SEC (in), VLV_FB1 (in), VLV_FB1 (out), VLV_FB (in), VLV_FB (out), Vout_SNS+ (in)

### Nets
SGND: C200.2 C201.2 C202.2 C203.2 C205.2 C210.2 C211.1 C213.2 C214.2 C215.2 C216.2 C217.2 C218.2 C219.2 J200.7 J200.10 J200.13 J200.16 J200.19 J200.22 J200.29 J200.35 J200.38 J200.46 J200.47 J200.65 J200.83 J200.97 J200.111 J201.2 J201.4 J201.19 J201.20 R202.1 R207.1 R208.1 R209.1 R212.2 R222.1 R225.1 R227.1 R231.1 R232.1 R234.1 R235.1 RT200.1 SGND#1.1 SGND#2.1 SGND#3.1 U201.1(PGND) U201.4(AGND) U201.9(PAD) U202.2(GND) U203.2(GND)
3V3s: C217.1 R213.1 U203.5(OUT) ; port 3V3s
5Vs: 5Vs.1 C211.2 C216.1 C218.1 J200.84 J200.98 J200.112 J201.1 J201.3 L200.2 R230.2 U201.6(VOS) U202.3(V+) U203.1(IN) U203.3(EN) ; port 5Vs
12VA: R223.1 R229.2 ; port 12VA
12VLS_EN: J200.58 J201.10 ; port 12VLS_EN
12VS: 12Vs.1 C215.1 C219.1 U201.2(VIN) U201.3(EN) ; port 12Vs
ACTIVE_EMI_SENSE_PSFB: J200.34 ; port ACTIVE_EMI_SENSE_PSFB
AD_IBUS: J200.24 ; port AD_IBUS
CS+: D201.2(A) D203.1(K) ; port CS+
CS-: D200.2(A) D202.1(K) ; port CS-
DAC_OUT: J200.9 ; port DAC_OUT
FAN_CTRL: J200.63 ; port FAN_CTRL
FAN_FB: J200.20 J201.13 ; port FAN_FB
IHV_FB: C202.1 J200.15 J201.9 R205.1 ; port IHV_FB
ILV_FB: C213.1 J200.14 J201.11 R224.2 R227.2 ; port ILV_FB
Iout_SNS: R226.1 ; port Iout_SNS
LEG1_FLT: R200.2 ; port LEG1_FLT
LEG1_HS: J200.49 J202.17 ; port LEG1_HS
LEG1_LS: J200.51 J202.19 ; port LEG1_LS
LEG2_FLT: R203.2 ; port LEG2_FLT
LEG2_HS: J200.53 J202.13 ; port LEG2_HS
LEG2_LS: J200.55 J202.15 ; port LEG2_LS
LEG3_HS: J200.50 J202.5 ; port LEG3_HS
LEG3_LS: J200.52 J202.7 ; port LEG3_LS
LEG4_HS: J200.54 J202.1 ; port LEG4_HS
LEG4_LS: J200.56 J202.3 ; port LEG4_LS
ORING_EN: J200.59 J202.4 ; port ORING_EN
PRI_FAULT_SEC: J200.74 J202.9 ; port PRI_FAULT_SEC
PSFB_ON: J200.68 J202.6 R225.2 R233.2 ; port PSFB_ON
PWM_ACL: J200.61 J202.11 ; port PWM_ACL
PWM_DEBUG_SEC: R211.1 ; port PWM_DEBUG_SEC
SEC_SCI_RX0: J200.76 ; port SEC_SCI_RX0
SEC_SCI_TX0: J200.78 ; port SEC_SCI_TX0
TMP_SEC: C205.1 J200.12 J201.12 R213.2 RT200.2 ; port TMP_SEC
VLV_FB: C214.1 J200.23 J201.17 R228.1 R231.2 ; port VLV_FB
VLV_FB1: C210.1 J200.17 J201.15 R220.1 R222.2 ; port VLV_FB1
Vout_SNS+: R221.2 ; port Vout_SNS+
NetC200_1: C200.1 R200.1 R201.2 R202.2
NetC201_1: C201.1 R203.1 R204.2 R207.2
NetC203_1: C203.1 J200.57 R211.2
NetC212_1: C212.1 R223.2 U202.5(VIN-)
NetC212_2: C212.2 R226.2 U202.4(VIN+)
NetD200_1: D200.1(K) D201.1(K) R206.1 R210.1
NetD202_2: D202.2(A) D203.2(A) R210.2 R212.1
NetJ200_62: J200.62 R201.1
NetJ200_64: J200.64 R204.1
NetL200_1: L200.1 U201.7(SW)
NetPSON_1: PSON.1 R233.1
NetR205_2: R205.2 R206.2 R208.2 R209.2 R234.2 R235.2
NetR220_2: R220.2 R221.1
NetR224_1: R224.1 U202.1(OUT)
NetR228_2: R228.2 R229.1
NetR230_1: R230.1 R232.2 U201.5(FB)

Not connected (* = marked no-connect by the designer): J200 1* 2* 3* 4* 5* 6* 8* 11 18 21 25 26* 27* 28* 30* 31* 32* 33* 36* 37* 39* 40* 41* 42* 43* 44* 45* 48* 60* 66* 67 69 70* 71 72* 73* 75* 77* 79* 80* 81* 82* 85* 86* 87 88* 89* 90* 91* 92* 93* 94* 95* 96* 99* 100* 101* 102* 103* 104* 105* 106* 107* 108* 109* 110* 113* 114* 115* 116* 117* 118* 119* 120*; J201 5 6 7 8 14 16 18; J202 2 8 10 12 14 16 18 20; U201 8(PG)*; U203 4(NC)

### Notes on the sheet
- LEG4_HS/LS kept in case we want to try full wave rectifier later
- (near J201) Placeholder for custom C2000 Daughter Card
- 100V/V
- (near SGND#2) 12Vs
- 5Vs
- (near C218) 0.1Amax
- (near C217) 0.1Amax

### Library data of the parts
5Vs 12Vs = 5000: as 5Vp on sheet PMP23126_Main_PSFB
C200 C201 C203 = GRM155R70J103KA01D: CAP, CERM, 0.01uF, 6.3V, +/-10%, X7R, 0402; Manufacturer: MuRata; Polarized: N; CompType: Capacitor; U/M: EA; Cap_F: 0.00000001; Tolerance_%: 10; Value1: Unknown; VDC_V: 6.3; TaMin_C: -55; TaMax_C: 125
C202 = 885012205044: CAP, CERM, 1000 pF, 25 V,+/- 10%, X7R, 0402; Manufacturer: Wurth Elektronik; Polarized: N; CompType: Capacitor; Value: 1000pF; U/M: EA; Cap_F: 0.000000001; Tolerance_%: 10; VDC_V: 25; Value2: 25V; TaMin_C: -55; TaMax_C: 125; SizeArea_mm2: 0.5; SizeAreaWB_mm2: 3; SizeX_mm: 1; SizeZ_mm: 0.6; AEC Category: Q200
C205 = CMP-0006320-2: CAP, CERM, 470 pF, 50 V, +/- 10%, X7R, AEC-Q200 Grade 1, 0402; Manufacturer: TDK; TaMin_C: -55°C; ESR_ohm: 4.96489; Polarized: N; SizeAreaWB_mm2: 3; Value1: 4.96489 ohm; U/M: EA; Value: 470pF; TaMax_C: 125°C; SizeZ_mm: 0.6; SizeX_mm: 1; SizeY_mm: 0.5; Value2: 50V; CompType: Capacitor; AEC Qualified: Y; IRMS_A: 2.28414dA; AEC Category: Q200
C210 C214 = 06035A102KAT2A: CAP, CERM, 1000pF, 50V, +/-10%, C0G/NP0, 0603; Manufacturer: AVX; Polarized: N; CompType: Capacitor; U/M: EA; Cap_F: 0.000000001; Tolerance_%: 10; ESR_Ohm: 0.048; Value1: 0.048 ohm; VDC_V: 50; TaMin_C: -55; TaMax_C: 125
C211 = C1608X7R1E105K080AB: CAP, CERM, 1uF, 25V, +/-10%, X7R, 0603; Manufacturer: TDK; Polarized: N; CompType: Capacitor; U/M: EA; Cap_F: 0.000001; Tolerance_%: 10; Value1: Unknown; VDC_V: 25; TaMin_C: -55; TaMax_C: 125
C212 = GRM1555C1E4R7CA01D: CAP, CERM, 4.7 pF, 25 V,+/- 5%, C0G/NP0, 0402; Manufacturer: MuRata; Polarized: N; CompType: Capacitor; Value: 4.7pF; U/M: EA; Cap_F: 0.0000000000047; Tolerance_%: 5; VDC_V: 25; Value2: 25V; TaMin_C: -55; TaMax_C: 125; SizeArea_mm2: 0.5; SizeAreaWB_mm2: 3; SizeX_mm: 1; SizeZ_mm: 0.6; AEC Category: Q200; Green_Lifecycle: Active; Green_REACh: Passed
C213 = CMP-0064911-2: CAP, CERM, 10 pF, 50 V,+/- 2.5%, C0G/NP0, AEC-Q200 Grade 1, 0402; Manufacturer: AVX; TaMin_C: -55°C; Polarized: N; SizeAreaWB_mm2: 3; Value1: Unknown; U/M: EA; Value: 10pF; TaMax_C: 125°C; SizeZ_mm: 0.6; SizeX_mm: 1; SizeY_mm: 0.5; CompType: Capacitor; AEC Qualified: Y; AEC Category: Q200
C215 = CMP-0007728-2: CAP, CERM, 1 uF, 25 V, +/- 10%, X7R, 0805; Manufacturer: Kemet; TaMin_C: -55°C; Polarized: N; SizeAreaWB_mm2: 6.75; Value1: Unknown; U/M: EA; Value: 1uF; TaMax_C: 125°C; SizeZ_mm: 1.45; SizeX_mm: 2; SizeY_mm: 1.25; Cap_Case: 0805; SizeArea_mm2: 2.5; AEC Category: Q200
C216 = CMP-0007989-2: CAP, CERM, 22 uF, 6.3 V, +/- 10%, X5R, 0805; Manufacturer: Samsung Electro-Mechanics; TaMin_C: -55°C; Polarized: N; SizeAreaWB_mm2: 6.75; Value1: Unknown; U/M: EA; Value: 22uF; TaMax_C: 85°C; SizeZ_mm: 1.45; SizeX_mm: 2; SizeY_mm: 1.25; Cap_Case: 0805; SizeArea_mm2: 2.5; Cap_F: 22µF; AEC Category: Q200
C217 C218 = GRM155R70J104KA01D: CAP, CERM, 0.1uF, 6.3V, +/-10%, X7R, 0402; Manufacturer: MuRata; Polarized: N; CompType: Capacitor; U/M: EA; Cap_F: 0.0000001; Tolerance_%: 10; Value1: Unknown; VDC_V: 6.3; TaMin_C: -55; TaMax_C: 125
C219 = GCM31CR71C106KA64L: as C108 on sheet PMP23126_Main_PSFB
D200-D203 = BAS316,115: Diode, Ultrafast, 100 V, 0.25 A, SOD-323; Manufacturer: Nexperia; U/M: EA; Vf_V: 1.4; Value: 100V; Value1: 0.25A; Value2: 1.4V; Io_A: 0.25; Vr_V: 100; TJmax_C: 150; SizeAreaWB_mm2: 8.695; SizeArea_mm2: 3.645; SizeX_mm: 2.7; SizeY_mm: 1.35; SizeZ_mm: 1; AEC Category: Q101; Green_Lifecycle: Not Set; Green_REACh: Incomplete
J200 = controlCARD-120HSEC: C2000 controlCARD-120HSEC connector, SMT; Manufacturer: Samtec; SymbolCreator: a0412235; Note: The pin numbering does not match Samtec datasheet
J201 J202 = CMP-0750170-1: Header, 1.27mm, 10x2, Gold, TH; Manufacturer: Sullins Connector Solutions; Row_Count: 2; Shrouded: N; Pitch_mm: 1.27; Cert_UL: Y; Gender: Male; Current_A: 1A; Voltage_V: 500V
L200 = CMP-0087867-1: as L101 on sheet PMP23126_Main_PSFB
PSON = 5003: Test Point, Miniature, Orange, TH; Manufacturer: Keystone; CompType: Test Point Loop; ContactFinish: Silver; Green_Lifecycle: Active; Green_REACh: Passed
R200 R203 = CRCW04024K99FKED: RES, 4.99 k, 1%, 0.063 W, 0402; Manufacturer: Vishay-Dale; CompType: Resistor; Value: 4.99k; Res_ohm: 4990; Value_Code: 4k99; Tolerance_%: 1; Power_W: 0.063; Value2: 0.063W; VDC_V: 50; TempCo: 100 ppm/C; SizeArea_mm2: 0.5; SizeZ_mm: 0.6; EIA_Code: E96; U/M: EA; AEC Category: Q200
R201 R204 R221 R229 = CRCW0603100RFKEA: RES, 100, 1%, 0.1 W, 0603; Manufacturer: Vishay-Dale; CompType: Resistor; Value: 100; Value_Code: 100R; Tolerance_%: 1; Power_W: 0.1; Value2: 0.1W; VDC_V: 75; TempCo: 100 ppm/C; SizeArea_mm2: 1.28; SizeX_mm: 1.6; SizeY_mm: 0.8; EIA_Code: E96; U/M: EA; AEC Category: Q200; Green_Lifecycle: Active; Green_REACh: Passed
R202 R207 = CRCW04029K31FKED: RES, 9.31 k, 1%, 0.063 W, 0402; Manufacturer: Vishay-Dale; CompType: Resistor; Value: 9.31k; Res_ohm: 9310; Value_Code: 9k31; Tolerance_%: 1; Power_W: 0.063; Value2: 0.063W; VDC_V: 50; TempCo: 100 ppm/C; SizeArea_mm2: 0.5; SizeZ_mm: 0.6; EIA_Code: E96; U/M: EA; AEC Category: Q200
R205 = ATC504L1000FTNCFT: RES, 100, 1%, 0.125 W, AEC-Q200 Grade 1, 0402; Manufacturer: AT Ceramics; CompType: Resistor; Value: 100; Value_Code: 100R; Tolerance_%: 1; Power_W: 0.125; Value2: 0.125W; TempCo: ppm/C; SizeArea_mm2: 0.5; SizeZ_mm: 0.6; EIA_Code: E96; U/M: EA; AEC Category: Q200; AEC Qualified: Y
R206 R212 = CRCW04020000Z0ED: RES, 0, 5%, 0.063 W, 0402; Manufacturer: Vishay-Dale; CompType: Resistor; Value: 0; Value_Code: 0000; Tolerance_%: 5; Power_W: 0.063; Value2: 0.063W; VDC_V: 50; TempCo: 200 ppm/C; SizeArea_mm2: 0.5; SizeX_mm: 1; SizeZ_mm: 0.6; EIA_Code: E24; U/M: EA; AEC Category: Q200; Green_Lifecycle: Active; Green_REACh: Passed
R208 R209 R234 R235 = CRCW120614R7FKEA: RES, 14.7, 1%, 0.25 W, 1206; Manufacturer: Vishay-Dale; CompType: Resistor; Value: 14.7; Value_Code: 14R7; Tolerance_%: 1; Power_W: 0.25; Value2: 0.25W; VDC_V: 200; TempCo: 100 ppm/C; SizeArea_mm2: 5.12; SizeX_mm: 3.2; SizeY_mm: 1.6; SizeZ_mm: 1.35; EIA_Code: E96; U/M: EA; AEC Category: Q200
R210 = RC0603FR-079k76L: RES, 9.76 k, 1%, 0.1 W, 0603; Manufacturer: Yageo America; CompType: Resistor; Value: 9.76k; Res_ohm: 9760; Value_Code: 9k76; Tolerance_%: 1; Power_W: 0.1; Value2: 0.1W; VDC_V: 150; TempCo: 200 ppm/C; SizeArea_mm2: 1.28; SizeX_mm: 1.6; SizeY_mm: 0.8; EIA_Code: E96; U/M: EA; AEC Category: Q200
R211 = CRCW04021K40FKED: RES, 1.40k ohm, 1%, 0.063W, 0402; Manufacturer: Vishay-Dale; CompType: Resistor; Res_ohm: 1400; Value_Code: 1k40; Tolerance_%: 1; Power_W: 0.063; VDC_V: 50; TempCo: 100 ppm/C; EIA_Code: E96; U/M: EA
R213 = CRCW040210K0FKED: RES, 10.0 k, 1%, 0.063 W, 0402; Manufacturer: Vishay-Dale; CompType: Resistor; Value: 10.0k; Res_ohm: 10000; Value_Code: 10k0; Tolerance_%: 1; Power_W: 0.063; Value2: 0.063W; VDC_V: 50; TempCo: 100 ppm/C; SizeArea_mm2: 0.5; SizeZ_mm: 0.6; EIA_Code: E96; U/M: EA; AEC Category: Q200
R220 R228 = CRCW120637K4FKEA: RES, 37.4 k, 1%, 0.25 W, 1206; Manufacturer: Vishay-Dale; CompType: Resistor; Value: 37.4k; Res_ohm: 37400; Value_Code: 37k4; Tolerance_%: 1; Power_W: 0.25; Value2: 0.25W; VDC_V: 200; TempCo: 100 ppm/C; SizeArea_mm2: 5.12; SizeX_mm: 3.2; SizeY_mm: 1.6; SizeZ_mm: 1.35; EIA_Code: E96; U/M: EA; AEC Category: Q200
R222 R231 = RC0603FR-071K82L: RES, 1.82 k, 1%, 0.1 W, 0603; Manufacturer: Yageo America; CompType: Resistor; Value: 1.82k; Res_ohm: 1820; Value_Code: 1k82; Tolerance_%: 1; Power_W: 0.1; Value2: 0.1W; VDC_V: 150; TempCo: 200 ppm/C; EIA_Code: E96; U/M: EA; SizeArea_mm2: 1.28; SizeX_mm: 1.6; SizeY_mm: 0.8; AEC Category: Q200; Green_Lifecycle: Active; Green_REACh: Passed
R223 R226 = RC0603FR-074R75L: RES, 4.75, 1%, 0.1 W, 0603; Manufacturer: Yageo America; CompType: Resistor; Value: 4.75; Value_Code: 4R75; Tolerance_%: 1; Power_W: 0.1; Value2: 0.1W; VDC_V: 150; TempCo: 200 ppm/C; SizeArea_mm2: 1.28; SizeX_mm: 1.6; SizeY_mm: 0.8; EIA_Code: E96; U/M: EA; AEC Category: Q200
R224 = CRCW06032K49FKEA: RES, 2.49 k, 1%, 0.1 W, 0603; Manufacturer: Vishay-Dale; CompType: Resistor; Value: 2.49k; Res_ohm: 2490; Value_Code: 2k49; Tolerance_%: 1; Power_W: 0.1; Value2: 0.1W; VDC_V: 75; TempCo: 100 ppm/C; SizeArea_mm2: 1.28; SizeX_mm: 1.6; SizeY_mm: 0.8; EIA_Code: E96; U/M: EA; AEC Category: Q200; Green_Lifecycle: Active; Green_REACh: Passed
R225 = CRCW120610K0FKEA: RES, 10.0 k, 1%, 0.25 W, 1206; Manufacturer: Vishay-Dale; CompType: Resistor; Value: 10.0k; Res_ohm: 10000; Value_Code: 10k0; Tolerance_%: 1; Power_W: 0.25; Value2: 0.25W; VDC_V: 200; TempCo: 100 ppm/C; SizeArea_mm2: 5.12; SizeX_mm: 3.2; SizeY_mm: 1.6; SizeZ_mm: 1.35; EIA_Code: E96; U/M: EA; AEC Category: Q200; Green_Lifecycle: Active; Green_REACh: Passed
R227 = CRCW06037K50FKEA: RES, 7.50 k, 1%, 0.1 W, 0603; Manufacturer: Vishay-Dale; CompType: Resistor; Value: 7.50k; Res_ohm: 7500; Value_Code: 7k50; Tolerance_%: 1; Power_W: 0.1; Value2: 0.1W; VDC_V: 75; TempCo: 100 ppm/C; SizeArea_mm2: 1.28; SizeX_mm: 1.6; SizeY_mm: 0.8; EIA_Code: E96; U/M: EA; AEC Category: Q200; Green_Lifecycle: Active; Green_REACh: Passed
R230 = CMP-0026504-2: RES, 681 k, 1%, 0.063 W, AEC-Q200 Grade 0, 0402; Manufacturer: Vishay-Dale; Power_W: 63mW; TempCo: 100 ppm/C; Value: 681k; EIA_Code: E96; SizeX_mm: 1; SizeY_mm: 0.5; SizeZ_mm: 0.6; Value2: 0.063W; AEC Qualified: Y; VDC_V: 50V; AEC Category: Q200; AEC Grade: 0
R232 = CMP-0025997-3: RES, 130 k, 1%, 0.063 W, AEC-Q200 Grade 0, 0402; Manufacturer: Vishay-Dale; Power_W: 63mW; TempCo: 100 ppm/C; Value: 130k; EIA_Code: E96; SizeX_mm: 1; SizeY_mm: 0.5; SizeZ_mm: 0.6; Value2: 0.063W; AEC Qualified: Y; VDC_V: 50V; AEC Category: Q200; AEC Grade: 0
R233 = CRCW04021K00FKED: RES, 1.00 k, 1%, 0.063 W, 0402; Manufacturer: Vishay-Dale; CompType: Resistor; Value: 1.00k; Res_ohm: 1000; Value_Code: 1k00; Tolerance_%: 1; Power_W: 0.063; Value2: 0.063W; VDC_V: 50; TempCo: 100 ppm/C; SizeArea_mm2: 0.5; SizeZ_mm: 0.6; EIA_Code: E96; U/M: EA; AEC Category: Q200; Green_Lifecycle: Active; Green_REACh: Passed
RT200 = CMP-0084566-1: Thermistor, DEC0002A (X1SON-2); Alternate Manufacturer: Texas Instruments; Alternate PartNumber: TMP6131DECT; CompType: IC; AEC Category: Q200; SizeX_mm: 1; AEC Qualified: N; SizeZ_mm: 0.5; SizeArea_mm2: 0.6; SizeAreaWB_mm2: 3.2
SGND#1-SGND#3 = 5001: as PGND#2 on sheet PMP23126_Main_PSFB
U201 = CMP-0067100-2: as U100 on sheet PMP23126_Main_PSFB
U202 = CMP-0750220-2: INA293 High-Voltage, High Bandwidth, Unidirectional, 110-V Common-Mode, Current-Sense Amplifier, DBV0005A (SOT-23-5); Alternate PartNumber: INA293B3IDBVT; Manufacturer: Texas Instruments; AEC Category: Q200; AEC Qualified: N; SizeAreaWB_mm2: 14.82; SizeX_mm: 2.8; SizeZ_mm: 1.45; CompType: IC; SizeArea_mm2: 8.12; SizeY_mm: 2.9
U203 = TLV71333PQDBVRQ1: Capacitor-Free, 150-mA, Low-Dropout Regulator with Foldback Current Limit for Portable Devices, DBV0005A; Manufacturer: Texas Instruments; SymbolCreator: Altium; SizeArea_mm2: 8.12; SizeAreaWB_mm2: 14.82; SizeX_mm: 2.8; SizeY_mm: 2.9; SizeZ_mm: 1.45; CompType: IC; U/M: EA

## Sheet Output_Decoupling.SchDoc
size 431 x 279 mm; Date: Not shown in title block; ApprovedBy: Not shown in title block; CheckedBy: Not shown in title block; Author: Not shown in title block; CompanyName: Not shown in title block; Engineer: Not shown in title block; Organization: Not shown in title block; Address1: Not shown in title block; Address2: Not shown in title block; Address3: Not shown in title block; Address4: Not shown in title block; DocumentNumber: 1; Revision: Use project parameter SCH_Rev; SheetNumber: 1; SheetTotal: 1; PageSetup: Record=PageOptions¦CenterHorizontal=True¦CenterVertical=True¦PrintScale=1.00¦XCorrection=1.00¦YCorrection=1.00¦PrintKind=0¦BorderSize=5000000¦LeftOffset=0¦BottomOffset=0¦Orientation=2¦PaperLength=1000¦PaperWidth=1000¦Scale=100¦PaperSource=15¦PrintQuality=600¦MediaType=1¦DitherType=10¦PaperKind=Letter¦PrintScaleMode=1
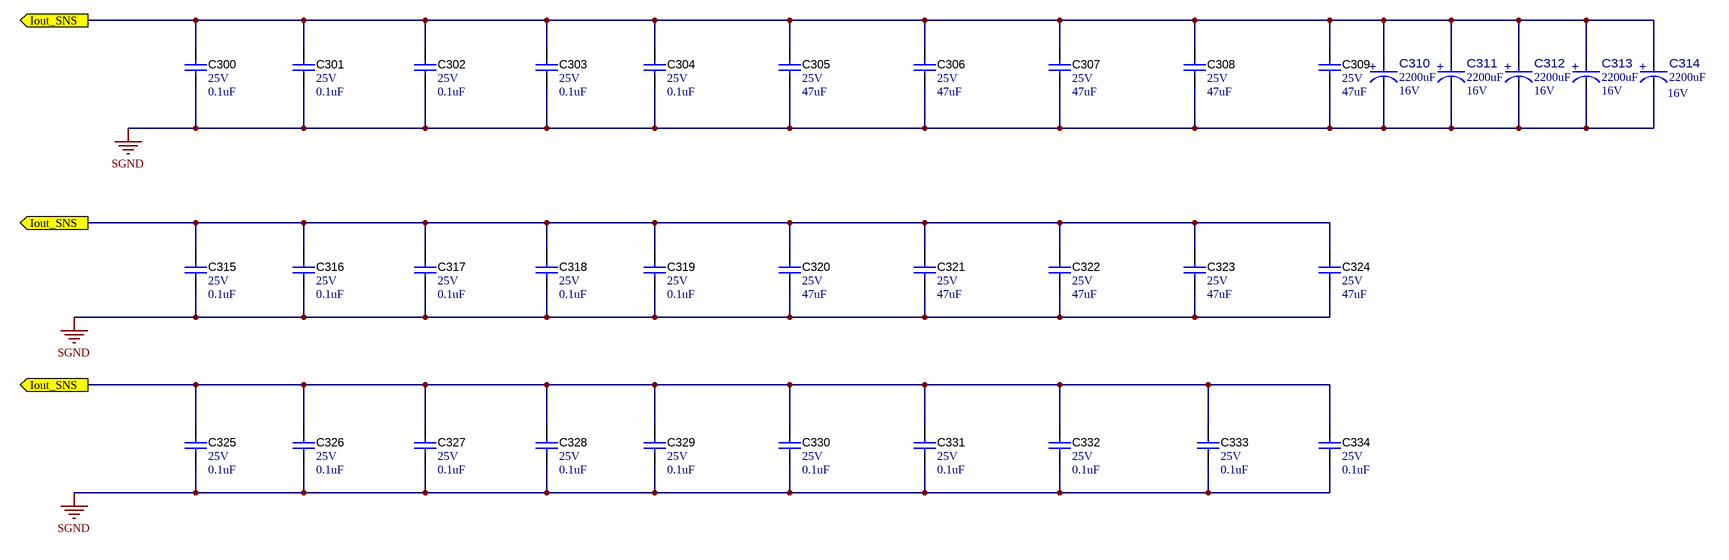
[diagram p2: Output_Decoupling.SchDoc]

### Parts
C300  VDC_V: 25V  ValueDisplayed: 0.1uF  [1206_180]  (hidden comment: GRM31C5C1E104JA01L)
C301  VDC_V: 25V  ValueDisplayed: 0.1uF  [1206_180]  (hidden comment: GRM31C5C1E104JA01L)
C302  VDC_V: 25V  ValueDisplayed: 0.1uF  [1206_180]  (hidden comment: GRM31C5C1E104JA01L)
C303  VDC_V: 25V  ValueDisplayed: 0.1uF  [1206_180]  (hidden comment: GRM31C5C1E104JA01L)
C304  VDC_V: 25V  ValueDisplayed: 0.1uF  [1206_180]  (hidden comment: GRM31C5C1E104JA01L)
C305  VDC_V: 25V  ValueDisplayed: 47uF  [1206_190]  (hidden comment: C3216X5R1E476M160AC)
C306  VDC_V: 25V  ValueDisplayed: 47uF  [1206_190]  (hidden comment: C3216X5R1E476M160AC)
C307  VDC_V: 25V  ValueDisplayed: 47uF  [1206_190]  (hidden comment: C3216X5R1E476M160AC)
C308  VDC_V: 25V  ValueDisplayed: 47uF  [1206_190]  (hidden comment: C3216X5R1E476M160AC)
C309  VDC_V: 25V  ValueDisplayed: 47uF  [1206_190]  (hidden comment: C3216X5R1E476M160AC)
C310  ValueDisplayed: 2200uF  VDC_V: 16V  [FP-APSG160ELL222MJ20S_RADIAL-MFG]  (hidden comment: APSG160ELL222MJ20S)
C311  ValueDisplayed: 2200uF  VDC_V: 16V  [FP-APSG160ELL222MJ20S_RADIAL-MFG]  (hidden comment: APSG160ELL222MJ20S)
C312  ValueDisplayed: 2200uF  VDC_V: 16V  [FP-APSG160ELL222MJ20S_RADIAL-MFG]  (hidden comment: APSG160ELL222MJ20S)
C313  ValueDisplayed: 2200uF  VDC_V: 16V  [FP-APSG160ELL222MJ20S_RADIAL-MFG]  (hidden comment: APSG160ELL222MJ20S)
C314  ValueDisplayed: 2200uF  VDC_V: 16V  [FP-APSG160ELL222MJ20S_RADIAL-MFG]  (hidden comment: APSG160ELL222MJ20S)
C315  VDC_V: 25V  ValueDisplayed: 0.1uF  [1206_180]  (hidden comment: GRM31C5C1E104JA01L)
C316  VDC_V: 25V  ValueDisplayed: 0.1uF  [1206_180]  (hidden comment: GRM31C5C1E104JA01L)
C317  VDC_V: 25V  ValueDisplayed: 0.1uF  [1206_180]  (hidden comment: GRM31C5C1E104JA01L)
C318  VDC_V: 25V  ValueDisplayed: 0.1uF  [1206_180]  (hidden comment: GRM31C5C1E104JA01L)
C319  VDC_V: 25V  ValueDisplayed: 0.1uF  [1206_180]  (hidden comment: GRM31C5C1E104JA01L)
C320  VDC_V: 25V  ValueDisplayed: 47uF  [1206_190]  (hidden comment: C3216X5R1E476M160AC)
C321  VDC_V: 25V  ValueDisplayed: 47uF  [1206_190]  (hidden comment: C3216X5R1E476M160AC)
C322  VDC_V: 25V  ValueDisplayed: 47uF  [1206_190]  (hidden comment: C3216X5R1E476M160AC)
C323  VDC_V: 25V  ValueDisplayed: 47uF  [1206_190]  (hidden comment: C3216X5R1E476M160AC)
C324  VDC_V: 25V  ValueDisplayed: 47uF  [1206_190]  (hidden comment: C3216X5R1E476M160AC)
C325  VDC_V: 25V  ValueDisplayed: 0.1uF  [1206_180]  (hidden comment: GRM31C5C1E104JA01L)
C326  VDC_V: 25V  ValueDisplayed: 0.1uF  [1206_180]  (hidden comment: GRM31C5C1E104JA01L)
C327  VDC_V: 25V  ValueDisplayed: 0.1uF  [1206_180]  (hidden comment: GRM31C5C1E104JA01L)
C328  VDC_V: 25V  ValueDisplayed: 0.1uF  [1206_180]  (hidden comment: GRM31C5C1E104JA01L)
C329  VDC_V: 25V  ValueDisplayed: 0.1uF  [1206_180]  (hidden comment: GRM31C5C1E104JA01L)
C330  VDC_V: 25V  ValueDisplayed: 0.1uF  [1206_180]  (hidden comment: GRM31C5C1E104JA01L)
C331  VDC_V: 25V  ValueDisplayed: 0.1uF  [1206_180]  (hidden comment: GRM31C5C1E104JA01L)
C332  VDC_V: 25V  ValueDisplayed: 0.1uF  [1206_180]  (hidden comment: GRM31C5C1E104JA01L)
C333  VDC_V: 25V  ValueDisplayed: 0.1uF  [1206_180]  (hidden comment: GRM31C5C1E104JA01L)
C334  VDC_V: 25V  ValueDisplayed: 0.1uF  [1206_180]  (hidden comment: GRM31C5C1E104JA01L)

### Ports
Iout_SNS (out)

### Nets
SGND: C300.2 C301.2 C302.2 C303.2 C304.2 C305.2 C306.2 C307.2 C308.2 C309.2 C310.1(CATHODE) C311.1(CATHODE) C312.1(CATHODE) C313.1(CATHODE) C314.1(CATHODE) C315.2 C316.2 C317.2 C318.2 C319.2 C320.2 C321.2 C322.2 C323.2 C324.2 C325.2 C326.2 C327.2 C328.2 C329.2 C330.2 C331.2 C332.2 C333.2 C334.2
Iout_SNS: C300.1 C301.1 C302.1 C303.1 C304.1 C305.1 C306.1 C307.1 C308.1 C309.1 C310.2(ANODE) C311.2(ANODE) C312.2(ANODE) C313.2(ANODE) C314.2(ANODE) C315.1 C316.1 C317.1 C318.1 C319.1 C320.1 C321.1 C322.1 C323.1 C324.1 C325.1 C326.1 C327.1 C328.1 C329.1 C330.1 C331.1 C332.1 C333.1 C334.1 ; port Iout_SNS

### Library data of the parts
C300-C304 C315-C319 = CMP-0064950-2: CAP, CERM, 0.1 uF, 25 V,+/- 5%, C0G/NP0, 1206; Manufacturer: MuRata; TaMin_C: -55°C; Polarized: N; SizeAreaWB_mm2: 10.92; Value1: Unknown; U/M: EA; Value: 0.1uF; TaMax_C: 125°C; SizeZ_mm: 1.8; SizeX_mm: 3.2; SizeY_mm: 1.6; Cap_Case: 1206; SizeArea_mm2: 5.12; CompType: Capacitor; Cap_F: 100nF; AEC Category: Q200
C305-C309 C320-C324 = CMP-0008656-2: CAP, CERM, 47 uF, 25 V, +/- 20%, X5R, 1206_190; Manufacturer: TDK; TaMin_C: -55°C; Polarized: N; SizeAreaWB_mm2: 10.92; Value1: Unknown; U/M: EA; Value: 47uF; TaMax_C: 85°C; SizeZ_mm: 1.9; SizeX_mm: 3.2; SizeY_mm: 1.6; Cap_Case: 1206; SizeArea_mm2: 5.12; Cap_F: 47µF; AEC Category: Q200
C310-C314 = CMP-0094633-1: 2200 µF 16 V Aluminum - Polymer Capacitors Radial, Can 8mOhm 20000 Hrs @ 105°C; Manufacturer: United Chemi-Con; Life: 20000Hours; SizeZ_mm: 21.5mm; Cap_F: 2.2mF; AEC Qualified: No; Value: 2.2mF; Tolerance_%: 20%; Dissipation Factor: 12%; Esr: 8m; IRMS_A: 8.1A; Leakage Current: 7040uA
C325-C334 = CMP-0064950-2: CAP, CERM, 0.1 uF, 25 V,+/- 5%, C0G/NP0, 1206; Manufacturer: MuRata; TaMin_C: -55°C; Polarized: N; SizeAreaWB_mm2: 10.92; Value1: Unknown; U/M: EA; Value: 0.1uF; TaMax_C: 125°C; SizeZ_mm: 1.8; SizeX_mm: 3.2; SizeY_mm: 1.6; Cap_Case: 1206; SizeArea_mm2: 5.12; Cap_F: 100nF; AEC Category: Q200

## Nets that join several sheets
SGND: PMP23126_Main_PSFB (20 pins), PMP23126_Main_Controller (54 pins), Output_Decoupling (35 pins)
5Vs: PMP23126_Main_PSFB (J100#2.2 J100#2.4 J101.10 J105.10), PMP23126_Main_Controller (15 pins)
12VS: PMP23126_Main_PSFB (D101.1 J100#1.5 J100#1.11), PMP23126_Main_Controller (5 pins)
CS+: PMP23126_Main_PSFB (CT100.1), PMP23126_Main_Controller (D201.2 D203.1)
CS-: PMP23126_Main_PSFB (CT100.3), PMP23126_Main_Controller (D200.2 D202.1)
Iout_SNS: PMP23126_Main_PSFB (L100.2 R102.2 R103.2), PMP23126_Main_Controller (R226.1), Output_Decoupling (35 pins)
LEG1_FLT: PMP23126_Main_PSFB (J101.3), PMP23126_Main_Controller (R200.2)
LEG1_HS: PMP23126_Main_PSFB (R105.2), PMP23126_Main_Controller (J200.49 J202.17)
LEG1_LS: PMP23126_Main_PSFB (R104.1), PMP23126_Main_Controller (J200.51 J202.19)
LEG2_FLT: PMP23126_Main_PSFB (J105.3), PMP23126_Main_Controller (R203.2)
LEG2_HS: PMP23126_Main_PSFB (R108.2), PMP23126_Main_Controller (J200.53 J202.13)
LEG2_LS: PMP23126_Main_PSFB (R106.1), PMP23126_Main_Controller (J200.55 J202.15)
LEG3_HS: PMP23126_Main_PSFB (J100#1.1), PMP23126_Main_Controller (J200.50 J202.5)
LEG3_LS: PMP23126_Main_PSFB (J100#1.3), PMP23126_Main_Controller (J200.52 J202.7)
LEG4_HS: PMP23126_Main_PSFB (J100#1.7), PMP23126_Main_Controller (J200.54 J202.1)
LEG4_LS: PMP23126_Main_PSFB (J100#1.9), PMP23126_Main_Controller (J200.56 J202.3)
PWM_ACL: PMP23126_Main_PSFB (J100#2.6), PMP23126_Main_Controller (J200.61 J202.11)
Vout_SNS+: PMP23126_Main_PSFB (R100.2), PMP23126_Main_Controller (R221.2)

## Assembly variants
001: not fitted R234 R235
